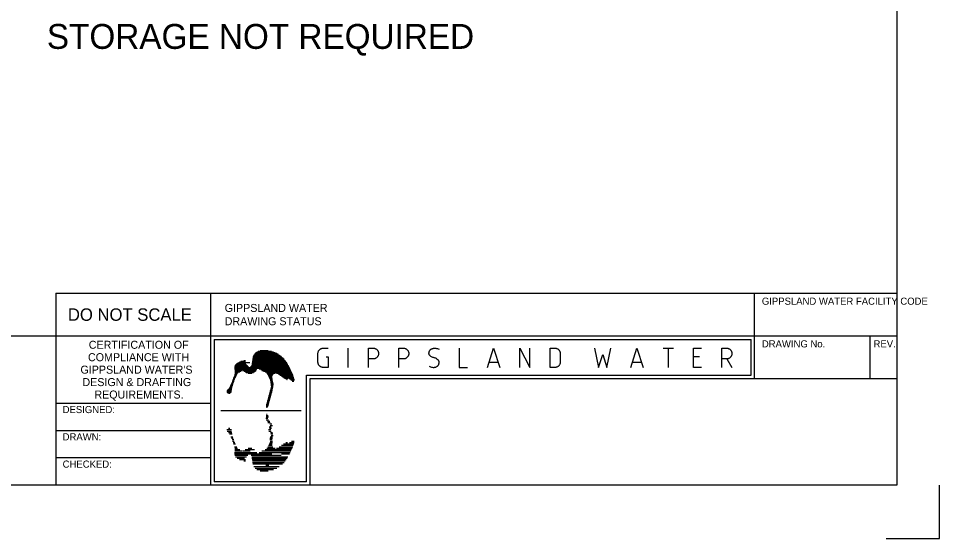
# Model space of a CAD drawing. Extents: x 0 to 841, y 0 to 594.
# Drawn here: x 582 to 841, y 0 to 146.3 of the extents above; entities that cross this region are included whole.
import ezdxf

# ---------------------------------------------------------------- set-up
doc = ezdxf.new("R2010")
doc.units = 0
doc.layers.add('A1BORDER', color=7, linetype='Continuous')
doc.layers.add('Level 1', color=7, linetype='Continuous')

msp = doc.modelspace()

# ---------------------------------------------------------------- linework, layer by layer
at = {"layer": 'A1BORDER'}
for p, q in [((829, 581), (829, 15)), ((592.5, 69), (592.5, 15)), ((592.5, 69), (829, 69)), ((636, 69), (636, 15)), ((789, 45), (789, 69)), ((28, 57), (829, 57)), ((821.5, 45), (821.5, 57)), ((637, 56), (788, 56)), ((637, 56), (637, 16)), ((788, 46), (788, 56)), ((648.37, 51.92), (655, 51.92)), ((648.53, 52.12), (654.64, 52.12)), ((648.74, 52.32), (654.24, 52.32)), ((649.02, 52.52), (653.76, 52.52)), ((649.39, 52.72), (653.15, 52.72)), ((650.01, 52.92), (652.2, 52.92)), ((643.54, 49.32), (645.57, 49.32)), ((643.85, 49.52), (647.09, 49.52)), ((644.18, 49.72), (645.89, 49.72)), ((644.54, 49.92), (645.36, 49.92)), ((645.37, 50.12), (645.86, 50.12)), ((647.66, 49.32), (657.57, 49.32)), ((647.69, 49.52), (657.44, 49.52)), ((647.71, 49.72), (657.31, 49.72)), ((647.75, 49.92), (657.17, 49.92)), ((647.78, 50.12), (657.02, 50.12)), ((647.81, 50.32), (656.86, 50.32)), ((647.85, 50.52), (656.69, 50.52)), ((647.88, 50.72), (656.5, 50.72)), ((647.91, 50.92), (656.3, 50.92)), ((647.96, 51.12), (656.08, 51.12)), ((648.03, 51.32), (655.85, 51.32)), ((648.12, 51.52), (655.59, 51.52)), ((648.23, 51.72), (655.31, 51.72)), ((642.73, 48.12), (658.25, 48.12)), ((642.74, 47.92), (658.35, 47.92)), ((642.75, 48.32), (646.79, 48.32)), ((642.79, 47.72), (649.08, 47.72)), ((642.81, 48.52), (646.55, 48.52)), ((642.83, 47.52), (648.95, 47.52)), ((642.85, 47.31), (644.88, 47.31)), ((642.87, 47.12), (644.57, 47.12)), ((642.88, 46.92), (644.23, 46.92)), ((642.88, 46.72), (643.83, 46.72)), ((642.9, 48.72), (646.37, 48.72)), ((643.04, 48.92), (646.16, 48.92)), ((643.26, 49.12), (645.9, 49.12)), ((645.14, 47.31), (648.83, 47.31)), ((645.49, 47.12), (648.67, 47.12)), ((645.76, 46.92), (648.42, 46.92)), ((646.05, 46.72), (648.11, 46.72)), ((647.19, 48.32), (658.14, 48.32)), ((647.42, 48.52), (658.03, 48.52)), ((647.54, 48.72), (657.92, 48.72)), ((647.61, 48.92), (657.8, 48.92)), ((647.63, 49.12), (657.68, 49.12)), ((649.72, 47.72), (658.45, 47.72)), ((650.12, 47.52), (658.55, 47.52)), ((650.48, 47.31), (658.64, 47.31)), ((650.87, 47.12), (658.73, 47.12)), ((651.36, 46.92), (658.82, 46.92)), ((651.76, 46.72), (658.9, 46.72)), ((642.06, 44.12), (642.55, 44.12)), ((642.13, 44.32), (642.62, 44.32)), ((642.21, 44.52), (642.69, 44.52)), ((642.28, 44.72), (642.76, 44.72)), ((642.35, 44.92), (642.83, 44.92)), ((642.43, 45.12), (642.9, 45.12)), ((642.5, 45.32), (643, 45.32)), ((642.57, 45.52), (643.1, 45.52)), ((642.65, 45.72), (643.2, 45.72)), ((642.72, 45.92), (643.3, 45.92)), ((642.79, 46.12), (643.4, 46.12)), ((642.84, 46.32), (643.5, 46.32)), ((642.87, 46.52), (643.6, 46.52)), ((646.62, 46.52), (647.67, 46.52)), ((651.88, 46.52), (654.15, 46.52)), ((651.99, 46.32), (653.71, 46.32)), ((652.1, 46.12), (653.52, 46.12)), ((652.2, 45.92), (653.4, 45.92)), ((652.31, 45.72), (653.33, 45.72)), ((652.41, 45.52), (653.31, 45.52)), ((652.5, 45.32), (653.34, 45.32)), ((652.6, 45.12), (653.38, 45.12)), ((652.69, 44.92), (653.41, 44.92)), ((652.78, 44.72), (653.44, 44.72)), ((652.83, 44.52), (653.48, 44.52)), ((652.86, 44.32), (653.53, 44.32)), ((652.89, 44.12), (653.57, 44.12)), ((654.57, 46.52), (658.99, 46.52)), ((655, 46.32), (659.07, 46.32)), ((655.31, 46.12), (659.14, 46.12)), ((655.62, 45.92), (659.22, 45.92)), ((655.93, 45.72), (659.29, 45.72)), ((656.24, 45.52), (659.35, 45.52)), ((656.55, 45.32), (659.42, 45.32)), ((656.86, 45.12), (657.74, 45.12)), ((657.17, 44.92), (657.68, 44.92)), ((657.51, 44.72), (657.54, 44.72)), ((657.91, 45.12), (659.48, 45.12)), ((658.19, 44.92), (659.54, 44.92)), ((658.47, 44.72), (659.59, 44.72)), ((658.75, 44.52), (659.58, 44.52)), ((659.02, 44.32), (659.47, 44.32)), ((663, 46), (788, 46)), ((663, 16), (663, 46)), ((664, 45), (829, 45)), ((664, 15), (664, 45)), ((640.63, 41.52), (641.93, 41.52)), ((640.73, 41.72), (641.95, 41.72)), ((640.9, 41.92), (641.97, 41.92)), ((641.1, 42.12), (642, 42.12)), ((641.25, 42.31), (642.04, 42.31)), ((641.37, 42.52), (642.09, 42.52)), ((641.46, 42.72), (642.15, 42.72)), ((641.55, 42.92), (642.2, 42.92)), ((641.64, 43.12), (642.25, 43.12)), ((641.73, 43.32), (642.3, 43.32)), ((641.82, 43.51), (642.35, 43.51)), ((641.91, 43.72), (642.41, 43.72)), ((641.99, 43.92), (642.48, 43.92)), ((652.74, 41.52), (653.37, 41.52)), ((652.79, 41.72), (653.41, 41.72)), ((652.85, 41.92), (653.45, 41.92)), ((652.9, 42.12), (653.49, 42.12)), ((652.91, 43.92), (653.62, 43.92)), ((652.94, 43.72), (653.67, 43.72)), ((652.95, 42.31), (653.53, 42.31)), ((652.97, 43.51), (653.71, 43.51)), ((652.99, 42.52), (653.57, 42.52)), ((653, 43.32), (653.69, 43.32)), ((653.02, 43.12), (653.67, 43.12)), ((653.03, 42.72), (653.61, 42.72)), ((653.05, 42.92), (653.64, 42.92)), ((640.62, 41.32), (641.88, 41.32)), ((640.72, 41.12), (641.73, 41.12)), ((641.03, 40.92), (641.43, 40.92)), ((652.03, 38.92), (652.66, 38.92)), ((652.09, 39.12), (652.72, 39.12)), ((652.14, 39.32), (652.77, 39.32)), ((652.2, 39.52), (652.82, 39.52)), ((652.25, 39.72), (652.88, 39.72)), ((652.3, 39.92), (652.93, 39.92)), ((652.36, 40.12), (652.99, 40.12)), ((652.41, 40.32), (653.04, 40.32)), ((652.47, 40.52), (653.1, 40.52)), ((652.52, 40.72), (653.15, 40.72)), ((652.57, 40.92), (653.2, 40.92)), ((652.63, 41.12), (653.26, 41.12)), ((652.68, 41.32), (653.31, 41.32)), ((636, 38), (592.5, 38)), ((651.63, 37.32), (652.23, 37.32)), ((651.64, 37.12), (652.17, 37.12)), ((651.65, 37.52), (652.28, 37.52)), ((651.71, 37.72), (652.34, 37.72)), ((651.76, 37.92), (652.39, 37.92)), ((651.79, 36.92), (651.9, 36.92)), ((651.82, 38.12), (652.44, 38.12)), ((651.87, 38.32), (652.5, 38.32)), ((651.92, 38.52), (652.55, 38.52)), ((651.98, 38.72), (652.61, 38.72)), ((638.93, 35.98), (661.47, 35.98)), ((651.54, 33.84), (652.17, 33.84)), ((651.63, 34.64), (652.23, 34.64)), ((651.71, 34.24), (652.34, 34.24)), ((651.79, 35.04), (651.9, 35.04)), ((651.65, 33.44), (652.28, 33.44)), ((652.03, 33.04), (652.66, 33.04)), ((652.14, 32.64), (652.77, 32.64)), ((652.47, 31.44), (653.1, 31.44)), ((652.66, 32.24), (653.29, 32.24)), ((652.77, 31.84), (653.4, 31.84)), ((636, 30.34), (592.5, 30.34)), ((640.62, 30.64), (641.88, 30.64)), ((640.73, 30.24), (641.95, 30.24)), ((641.03, 31.04), (641.43, 31.04)), ((641.1, 29.84), (642, 29.84)), ((641.37, 29.44), (642.09, 29.44)), ((641.73, 28.64), (642.3, 28.64)), ((652.34, 30.64), (652.97, 30.64)), ((652.45, 30.24), (653.07, 30.24)), ((652.57, 31.04), (653.2, 31.04)), ((652.77, 28.64), (653.46, 28.64)), ((652.9, 29.84), (653.49, 29.84)), ((652.99, 29.44), (653.57, 29.44)), ((653.05, 29.04), (653.64, 29.04)), ((641.91, 28.24), (642.41, 28.24)), ((642.06, 27.84), (642.55, 27.84)), ((642.21, 27.44), (642.69, 27.44)), ((642.35, 27.04), (642.83, 27.04)), ((642.5, 26.64), (643, 26.64)), ((652.31, 26.24), (653.33, 26.24)), ((652.5, 26.64), (653.34, 26.64)), ((652.66, 27.84), (653.35, 27.84)), ((652.69, 27.04), (653.41, 27.04)), ((652.72, 28.24), (653.44, 28.24)), ((652.83, 27.44), (653.48, 27.44)), ((655.93, 26.24), (659.29, 26.24)), ((656.55, 26.64), (659.42, 26.64)), ((657.17, 27.04), (657.68, 27.04)), ((658.19, 27.04), (659.54, 27.04)), ((658.75, 27.44), (659.58, 27.44)), ((642.73, 23.84), (653.27, 23.84)), ((642.79, 25.84), (643.4, 25.84)), ((642.79, 24.24), (649.08, 24.24)), ((642.81, 23.44), (646.55, 23.44)), ((642.85, 24.65), (644.88, 24.65)), ((642.87, 25.44), (643.6, 25.44)), ((642.88, 25.04), (644.23, 25.04)), ((645.14, 24.65), (647.18, 24.65)), ((645.76, 25.04), (648.42, 25.04)), ((646.62, 25.44), (647.67, 25.44)), ((647.42, 23.44), (655.89, 23.44)), ((649.72, 24.24), (658.45, 24.24)), ((650.48, 24.65), (658.64, 24.65)), ((651.36, 25.04), (658.82, 25.04)), ((651.88, 25.44), (654.15, 25.44)), ((652.1, 25.84), (653.52, 25.84)), ((654.57, 25.44), (658.99, 25.44)), ((655.31, 25.84), (659.14, 25.84)), ((655.94, 23.84), (658.25, 23.84)), ((636, 22.67), (592.5, 22.67)), ((643.04, 23.04), (646.16, 23.04)), ((643.54, 22.64), (645.57, 22.64)), ((644.18, 22.24), (645.89, 22.24)), ((645.37, 21.84), (645.86, 21.84)), ((647.61, 23.04), (657.8, 23.04)), ((647.66, 22.64), (657.57, 22.64)), ((647.71, 22.24), (657.31, 22.24)), ((647.78, 21.84), (657.02, 21.84)), ((647.85, 21.44), (656.69, 21.44)), ((647.91, 21.04), (656.3, 21.04)), ((648.23, 20.24), (655.31, 20.24)), ((648.53, 19.84), (654.64, 19.84)), ((649.02, 19.44), (653.76, 19.44)), ((650.01, 19.04), (652.2, 19.04)), ((651.57, 20.64), (652.44, 20.64)), ((663, 16), (637, 16)), ((829, 15), (28, 15)), ((829, 15), (829, 15)), ((841, 0), (841, 15)), ((826, 0), (841, 0))]:
    msp.add_line(p, q, dxfattribs=at)
for points in [[(668.49, 51.15), (669.06, 51.15), (669.06, 48.16), (667.64, 48.16), (667.51, 48.16), (667.39, 48.18), (667.28, 48.21), (667.15, 48.25), (667.04, 48.3), (666.93, 48.36), (666.82, 48.43), (666.73, 48.51), (666.64, 48.6), (666.55, 48.7), (666.48, 48.8), (666.41, 48.91), (666.35, 49.02), (666.31, 49.14), (666.27, 49.27), (666.24, 49.39), (666.22, 49.52), (666.22, 49.66), (666.22, 52.05), (666.22, 52.18), (666.24, 52.31), (666.27, 52.43), (666.31, 52.56), (666.35, 52.67), (666.41, 52.79), (666.48, 52.9), (666.55, 53), (666.64, 53.1), (666.73, 53.19), (666.82, 53.27), (666.93, 53.34), (667.04, 53.4), (667.15, 53.45), (667.28, 53.49), (667.39, 53.52), (667.51, 53.54), (667.64, 53.54), (669.06, 53.54)], [(674.74, 48.16), (674.74, 53.54)], [(680.42, 48.16), (680.42, 53.54), (681.84, 53.54), (681.96, 53.54), (682.08, 53.52), (682.2, 53.49), (682.32, 53.45), (682.43, 53.4), (682.54, 53.34), (682.65, 53.27), (682.74, 53.19), (682.84, 53.1), (682.92, 53), (682.99, 52.9), (683.06, 52.79), (683.12, 52.67), (683.17, 52.56), (683.21, 52.43), (683.23, 52.31), (683.25, 52.18), (683.26, 52.05), (683.25, 51.91), (683.23, 51.78), (683.21, 51.66), (683.17, 51.53), (683.12, 51.42), (683.06, 51.3), (682.99, 51.19), (682.92, 51.09), (682.84, 50.99), (682.74, 50.9), (682.65, 50.82), (682.54, 50.75), (682.43, 50.69), (682.32, 50.64), (682.2, 50.6), (682.08, 50.57), (681.96, 50.55), (681.84, 50.55), (680.42, 50.55)], [(688.93, 48.16), (688.93, 53.54), (690.35, 53.54), (690.47, 53.54), (690.59, 53.52), (690.71, 53.49), (690.83, 53.45), (690.94, 53.4), (691.05, 53.34), (691.16, 53.27), (691.26, 53.19), (691.35, 53.1), (691.43, 53), (691.51, 52.9), (691.57, 52.79), (691.63, 52.67), (691.68, 52.56), (691.72, 52.43), (691.75, 52.31), (691.76, 52.18), (691.77, 52.05), (691.76, 51.91), (691.75, 51.78), (691.72, 51.66), (691.68, 51.53), (691.63, 51.42), (691.57, 51.3), (691.51, 51.19), (691.43, 51.09), (691.35, 50.99), (691.26, 50.9), (691.16, 50.82), (691.05, 50.75), (690.94, 50.69), (690.83, 50.64), (690.71, 50.6), (690.59, 50.57), (690.47, 50.55), (690.35, 50.55), (688.93, 50.55)], [(697.45, 48.46), (697.67, 48.36), (697.9, 48.27), (698.12, 48.21), (698.36, 48.17), (698.6, 48.16), (698.84, 48.16), (698.87, 48.16), (699.03, 48.18), (699.18, 48.21), (699.33, 48.26), (699.48, 48.32), (699.62, 48.4), (699.72, 48.46), (699.81, 48.53), (699.9, 48.61), (699.98, 48.69), (700.05, 48.78), (700.11, 48.88), (700.17, 48.99), (700.22, 49.09), (700.25, 49.21), (700.28, 49.32), (700.29, 49.36), (700.3, 49.44), (700.3, 49.52), (700.3, 49.61), (700.29, 49.69), (700.27, 49.77), (700.25, 49.86), (700.22, 49.93), (700.18, 50.01), (700.14, 50.09), (700.09, 50.15), (700.04, 50.21), (700.01, 50.25), (699.85, 50.39), (699.69, 50.51), (699.52, 50.61), (699.34, 50.7), (699.15, 50.78), (698.95, 50.83), (698.87, 50.85), (698.68, 50.9), (698.49, 50.96), (698.3, 51.04), (698.12, 51.14), (697.96, 51.26), (697.8, 51.39), (697.73, 51.45), (697.67, 51.51), (697.62, 51.57), (697.58, 51.64), (697.53, 51.71), (697.5, 51.79), (697.47, 51.87), (697.46, 51.95), (697.44, 52.04), (697.43, 52.12), (697.43, 52.21), (697.44, 52.29), (697.45, 52.35), (697.47, 52.46), (697.51, 52.58), (697.55, 52.69), (697.61, 52.79), (697.67, 52.89), (697.74, 52.99), (697.82, 53.07), (697.9, 53.15), (697.99, 53.23), (698.02, 53.24), (698.15, 53.33), (698.3, 53.4), (698.44, 53.45), (698.6, 53.5), (698.75, 53.52), (698.87, 53.54), (699.11, 53.55), (699.35, 53.53), (699.58, 53.49), (699.82, 53.43), (700.04, 53.35), (700.27, 53.25)], [(705.96, 53.54), (705.96, 48.16), (708.23, 48.16)], [(713.91, 48.16), (715.61, 53.54), (717.32, 48.16)], [(722.99, 48.16), (722.99, 53.54), (725.83, 48.16), (725.83, 53.54)], [(731.52, 48.16), (731.52, 53.54), (732.94, 53.54), (733.06, 53.54), (733.18, 53.52), (733.3, 53.49), (733.42, 53.45), (733.53, 53.4), (733.64, 53.34), (733.75, 53.27), (733.84, 53.19), (733.94, 53.1), (734.02, 53), (734.09, 52.9), (734.16, 52.79), (734.22, 52.67), (734.27, 52.56), (734.31, 52.43), (734.33, 52.31), (734.35, 52.18), (734.36, 52.05), (734.36, 49.66), (734.35, 49.52), (734.33, 49.39), (734.31, 49.27), (734.27, 49.14), (734.22, 49.02), (734.16, 48.91), (734.09, 48.8), (734.02, 48.7), (733.94, 48.6), (733.84, 48.51), (733.75, 48.43), (733.64, 48.36), (733.53, 48.3), (733.42, 48.25), (733.3, 48.21), (733.18, 48.18), (733.06, 48.16), (732.94, 48.16), (731.52, 48.16)], [(744.01, 53.54), (745.14, 48.16), (746.28, 51.75), (747.41, 48.16), (748.55, 53.54)], [(754.22, 48.16), (755.92, 53.54), (757.63, 48.16)], [(763.31, 53.54), (766.15, 53.54)], [(764.73, 53.54), (764.73, 48.16)], [(774.09, 48.16), (771.82, 48.16), (771.82, 53.54), (774.09, 53.54)], [(779.78, 48.16), (779.78, 53.54), (781.2, 53.54), (781.32, 53.54), (781.44, 53.52), (781.56, 53.49), (781.68, 53.45), (781.79, 53.4), (781.9, 53.34), (782.01, 53.27), (782.1, 53.19), (782.2, 53.1), (782.28, 53), (782.35, 52.9), (782.42, 52.79), (782.48, 52.67), (782.53, 52.56), (782.56, 52.43), (782.59, 52.31), (782.61, 52.18), (782.61, 52.05), (782.61, 51.91), (782.59, 51.78), (782.56, 51.66), (782.53, 51.53), (782.48, 51.42), (782.42, 51.3), (782.35, 51.19), (782.28, 51.09), (782.2, 50.99), (782.1, 50.9), (782.01, 50.82), (781.9, 50.75), (781.79, 50.69), (781.68, 50.64), (781.56, 50.6), (781.44, 50.57), (781.32, 50.55), (781.2, 50.55), (779.78, 50.55)], [(714.48, 49.66), (716.75, 49.66)], [(754.79, 49.66), (757.06, 49.66)], [(773.53, 51.15), (771.82, 51.15)], [(781.2, 50.55), (782.61, 48.16)]]:
    msp.add_lwpolyline(points, dxfattribs=at)

# ---------------------------------------------------------------- texts
for s, height, p in [('GIPPSLAND WATER FACILITY CODE', 2, (791.03, 65.77)), ('DO NOT SCALE', 3.5, (595.92, 61.25)), ('GIPPSLAND WATER', 2.25, (640, 63.75)), ('DRAWING STATUS', 2.25, (640, 60)), ('CERTIFICATION OF', 2.25, (601.79, 53.39)), ('DRAWING No.', 2, (791.03, 53.77)), ('REV.', 2, (822.43, 53.77)), ('COMPLIANCE WITH', 2.25, (601.57, 49.89)), ("GIPPSLAND WATER'S", 2.25, (599.45, 46.39)), ('DESIGN & DRAFTING', 2.25, (600, 42.89)), ('REQUIREMENTS.', 2.25, (603.37, 39.39)), ('DESIGNED:', 2, (594.44, 35.29)), ('DRAWN:', 2, (594.44, 27.62)), ('CHECKED:', 2, (594.44, 19.95))]:
    msp.add_text(s, height=height, dxfattribs=at).set_placement(p)
at = {"layer": 'Level 1'}
msp.add_text('STORAGE NOT REQUIRED', height=7, rotation=360, dxfattribs=at).set_placement((590, 137.74))

doc.saveas('drawing.dxf')
